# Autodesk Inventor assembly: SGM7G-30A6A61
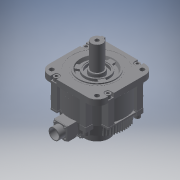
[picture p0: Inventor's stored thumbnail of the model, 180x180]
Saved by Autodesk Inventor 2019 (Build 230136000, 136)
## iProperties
Category: PARTsolutions
Company: YASKAWAUSA
Created: 2024-02
Part Number: SGM7G-30A6A61
Catalog Web Link: www.cadenas.de
Description: SGM7G-
Vendor: YASKAWAUSA
Document SubType Name: Assembly
Designer: psAdmin
Manufacturer: YASKAWAUSA
Mass: 3529.04 g
Surface Area: 2189.23 cm^2
Volume: 3529.04 cm^3
Density: 1 g/cm^3
Title: SGM7G-30A6A61
Author: Cadenas PARTsolutions
PSOL_IDENT_0: {$CADENAS_DATA/23d-libs/yaskawa_usa/motion/sigma_7_servo_products/rotary_servo_motors/sgm7g.prj},178
PSOL_IDENT_1: {STYP=ASS},{VTYP=3D},{NB=SGM7G-30A6A61},{LINA=SGM7G-30A6A61},{NN=SGM7G},{DATE=23.05.2022 13:08:23},
PSOL_IDENT_2: {GEOMDATE=02.02.2021 08:21:09},{VERSION=},{LINEID=1400},{WBVAR=},{WBNUMERIC=}  {NB=SGM7G-30A6A61},{L
PSOL_IDENT_3: INA=SGM7G-30A6A61},{KT=DUMMY},{SHA256=Ki2iMjxjCAhV01RQo1wHrteAobWMX14GeladcQJyvY8=},{INAME=00101__sg
PSOL_IDENT_4: m7g_30a6a612estep},{PN=SGM7G-30A6A61},{DESC=S7 MTR 3.0KW 200V BAT-LESS ABS KW TP},{SERIES=7G},{RATO=
PSOL_IDENT_5: 3000},{SV=200},{SE=batteryless 24-bit absolute},{DR=A},{SHE=straight with key and tap},{OPT=without
PSOL_IDENT_6: options}
NB: SGM7G-30A6A61
NN: SGM7G
NBSYN: $PN.
LINA: SGM7G-30A6A61
CATALOG: Yaskawa
PN: SGM7G-30A6A61
DESC: S7 MTR 3.0KW 200V BAT-LESS ABS KW TP
SERIES: 7G
RATO: 3000
SV: 200
SE: batteryless 24-bit absolute
DR: A
SHE: straight with key and tap
OPT: without options
SUPPLIER: YASKAWAUSA
ARTICLENO: SGM7G-30A6A61
BOMINFO: SGM7G-30A6A61
CREATOR: CADENAS GmbH
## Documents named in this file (3)
- e:\temp\worker_COMMON_2\temp\tmp_5148_20_zcujn\format_0\SGM7G-30A6A61.iam
- e:\temp\worker_COMMON_2\temp\tmp_5148_20_zcujn\format_0\SGM7G-30A6A61_PART1.ipt
- e:\temp\worker_COMMON_2\temp\tmp_5148_20_zcujn\format_0\SGM7G-30A6A61_PART2.ipt
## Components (2 placed, 2 different names)
1. SGM7G-30A6A61_PART1:1
2. SGM7G-30A6A61_PART2:1
